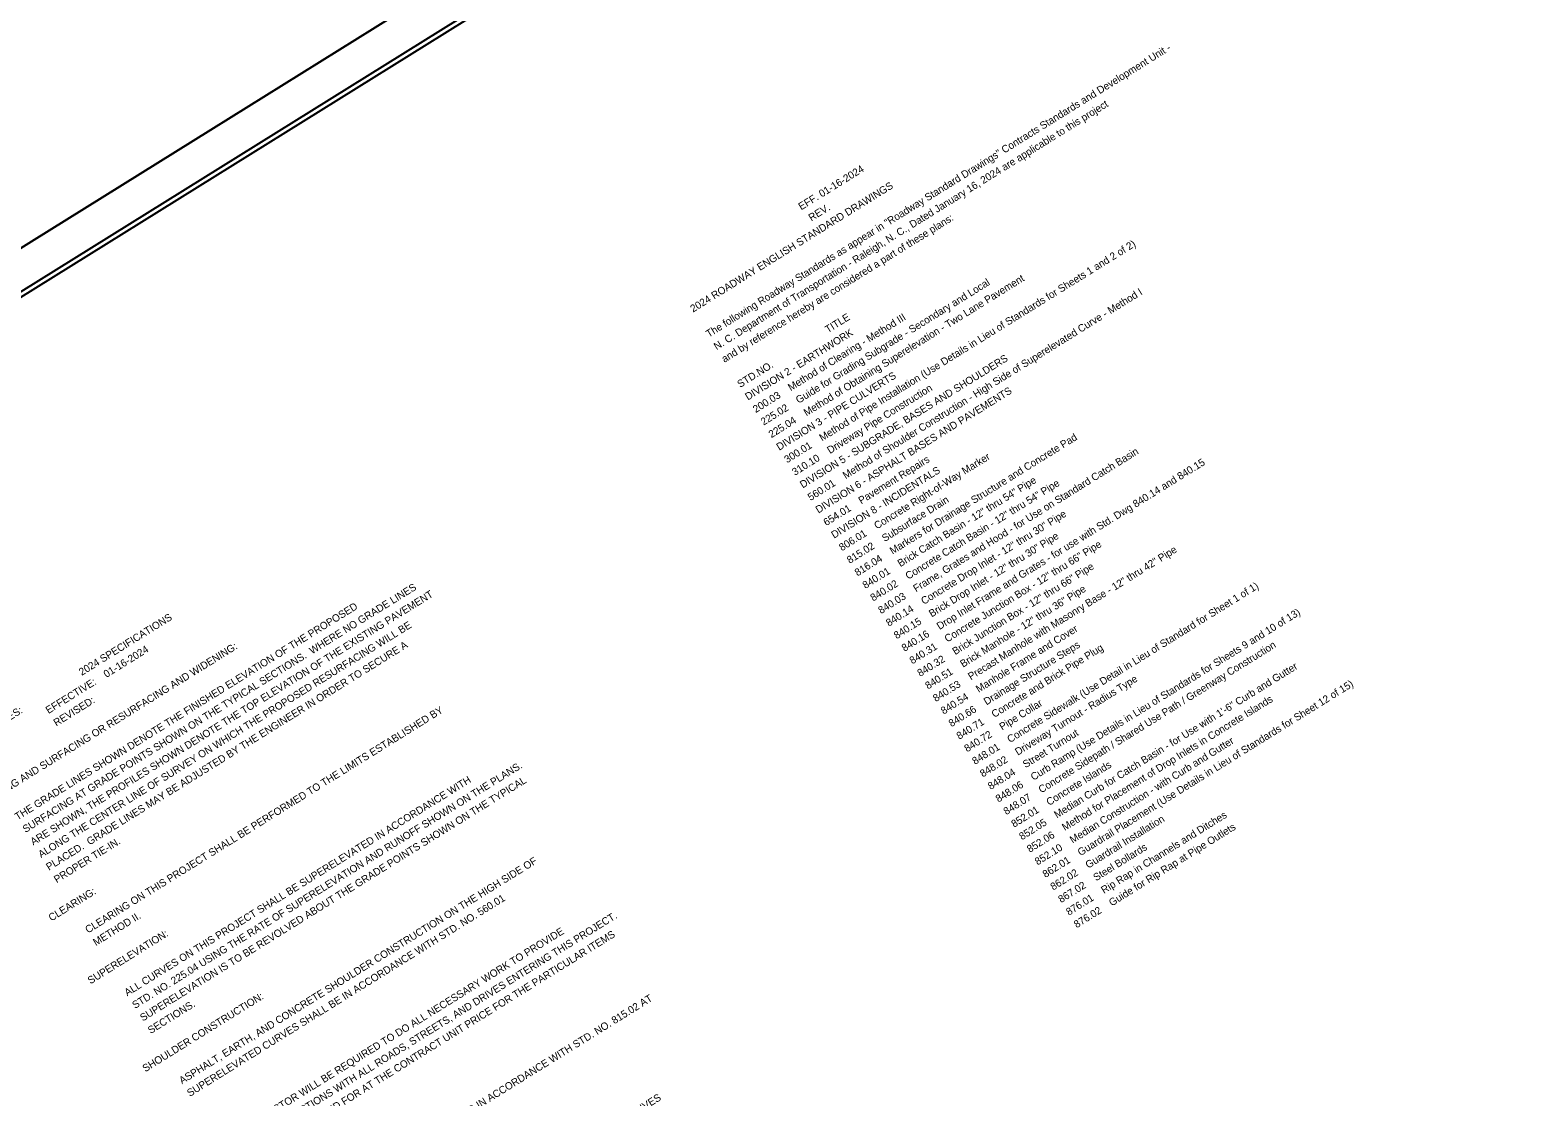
# Model space of a CAD drawing. Extents: x 2047559 to 2049567, y 759970 to 761789.
# Drawn here: x 2048269 to 2049084, y 760880 to 761456 of the extents above; entities that cross this region are included whole.
import ezdxf

# ---------------------------------------------------------------- set-up
doc = ezdxf.new("R2010")
doc.units = 0
for name, color, linetype in [('Sheet Cutting Line CELL', 7, 'Continuous'), ('Sheet Data Text CELL', 7, 'Continuous'), ('Sheet Plan CELL', 7, 'Continuous'), ('Sheet Plot Border Inside CELL', 7, 'Continuous'), ('Sheet Plot Border Outside CELL', 7, 'Continuous')]:
    doc.layers.add(name, color=color, linetype=linetype)

msp = doc.modelspace()

# ---------------------------------------------------------------- linework, layer by layer
at = {"layer": 'Sheet Cutting Line CELL'}
msp.add_line((2048987.97, 761789.33), (2047559, 760899.25), dxfattribs=at)
at = {"layer": 'Sheet Plan CELL'}
msp.add_lwpolyline([(2048985.43, 761761.24), (2047712.23, 760968.18), (2048267.37, 760076.94), (2049540.57, 760870)], close=True, dxfattribs=at)
at = {"layer": 'Sheet Plot Border Inside CELL'}
msp.add_lwpolyline([(2048138.4, 759993.66), (2049552.51, 760874.48), (2048994.72, 761769.97), (2047580.61, 760889.15)], close=True, dxfattribs=at)
at = {"layer": 'Sheet Plot Border Outside CELL'}
msp.add_lwpolyline([(2048137.94, 759969.81), (2049566.9, 760859.89), (2048987.97, 761789.33), (2047559, 760899.25)], close=True, dxfattribs=at)

# ---------------------------------------------------------------- texts
at = {"layer": 'Sheet Data Text CELL'}
for s, height, p in [('The following Roadway Standards as appear in "Roadway Standard Drawings" Contracts Standards and Development Unit -', 3.99997, (2048635.63, 761289.8)), ('N. C. Department of Transportation - Raleigh, N. C., Dated January 16, 2024 are applicable to this project', 3.99997, (2048639.86, 761283.01)), ('                                                     EFF. 01-16-2024', 4, (2048618.71, 761316.96)), ('2024 ROADWAY ENGLISH STANDARD DRAWINGS', 4, (2048627.17, 761303.38)), ('                                                      REV. ', 4, (2048622.94, 761310.17)), ('and by reference hereby are considered a part of these plans:', 4, (2048644.09, 761276.22)), ('300.01    Method of Pipe Installation (Use Details in Lieu of Standards for Sheets 1 and 2 of 2)', 4, (2048677.93, 761221.9)), ('225.02    Guide for Grading Subgrade - Secondary and Local', 4, (2048665.24, 761242.27)), ('225.04    Method of Obtaining Superelevation - Two Lane Pavement', 4, (2048669.47, 761235.48)), ('560.01    Method of Shoulder Construction - High Side of Superelevated Curve - Method I', 4, (2048690.62, 761201.53)), ('STD.NO.                       TITLE', 4, (2048652.55, 761262.64)), ('200.03    Method of Clearing - Method III', 4, (2048661.01, 761249.06)), ('DIVISION 2 - EARTHWORK', 4, (2048656.78, 761255.85)), ('DIVISION 5 - SUBGRADE, BASES AND SHOULDERS', 4, (2048686.39, 761208.32)), ('DIVISION 3 - PIPE CULVERTS', 4, (2048673.7, 761228.69)), ('310.10    Driveway Pipe Construction', 4, (2048682.16, 761215.11)), ('DIVISION 6 - ASPHALT BASES AND PAVEMENTS', 4, (2048694.85, 761194.74)), ('816.04    Markers for Drainage Structure and Concrete Pad', 4, (2048715.99, 761160.79)), ('654.01    Pavement Repairs', 4, (2048699.08, 761187.95)), ('806.01    Concrete Right-of-Way Marker', 4, (2048707.53, 761174.37)), ('840.03    Frame, Grates and Hood - for Use on Standard Catch Basin', 4, (2048728.68, 761140.41)), ('840.16    Drop Inlet Frame and Grates - for use with Std. Dwg 840.14 and 840.15', 4, (2048741.37, 761120.04)), ('DIVISION 8 - INCIDENTALS', 4, (2048703.31, 761181.16)), ('840.01    Brick Catch Basin - 12" thru 54" Pipe', 4, (2048720.22, 761153.99)), ('840.02    Concrete Catch Basin - 12" thru 54" Pipe', 4, (2048724.45, 761147.2)), ('815.02    Subsurface Drain', 4, (2048711.76, 761167.58)), ('840.14    Concrete Drop Inlet - 12" thru 30" Pipe', 4, (2048732.91, 761133.62)), ('840.15    Brick Drop Inlet - 12" thru 30" Pipe', 4, (2048737.14, 761126.83)), ('840.31    Concrete Junction Box - 12" thru 66" Pipe', 4, (2048745.6, 761113.25)), ('840.53    Precast Manhole with Masonry Base - 12" thru 42" Pipe', 4, (2048758.29, 761092.88)), ('840.32    Brick Junction Box - 12" thru 66" Pipe', 4, (2048749.83, 761106.46)), ('         SURFACING AT GRADE POINTS SHOWN ON THE TYPICAL SECTIONS.  WHERE NO GRADE LINES ', 4, (2048255.07, 761015.06)), ('         ARE SHOWN, THE PROFILES SHOWN DENOTE THE TOP ELEVATION OF THE EXISTING PAVEMENT ', 4, (2048259.3, 761008.27)), ('840.51    Brick Manhole - 12" thru 36" Pipe', 4, (2048754.06, 761099.67)), ('848.01    Concrete Sidewalk (Use Detail in Lieu of Standard for Sheet 1 of 1)', 4, (2048779.44, 761058.93)), ('         THE GRADE LINES SHOWN DENOTE THE FINISHED ELEVATION OF THE PROPOSED ', 4, (2048250.84, 761021.85)), ('848.06    Curb Ramp (Use Details in Lieu of Standards for Sheets 9 and 10 of 13)', 4, (2048792.13, 761038.56)), ('GENERAL NOTES:                         2024 SPECIFICATIONS', 4, (2048225.46, 761062.59)), ('         ALONG THE CENTER LINE OF SURVEY ON WHICH THE PROPOSED RESURFACING WILL BE ', 4, (2048263.53, 761001.48)), ('840.54    Manhole Frame and Cover', 4, (2048762.52, 761086.09)), ('         PLACED.  GRADE LINES MAY BE ADJUSTED BY THE ENGINEER IN ORDER TO SECURE A ', 4, (2048267.76, 760994.69)), ('GRADING AND SURFACING OR RESURFACING AND WIDENING:  ', 4, (2048242.38, 761035.43)), ('                                       EFFECTIVE:    01-16-2024', 4, (2048229.69, 761055.8)), ('840.66    Drainage Structure Steps', 4, (2048766.75, 761079.3)), ('840.71    Concrete and Brick Pipe Plug', 4, (2048770.98, 761072.51)), ('848.07    Concrete Sidepath / Shared Use Path / Greenway Construction', 4, (2048796.36, 761031.77)), ('852.05    Median Curb for Catch Basin - for Use with 1\'-6" Curb and Gutter', 4, (2048804.82, 761018.19)), ('848.02    Driveway Turnout - Radius Type', 4, (2048783.67, 761052.14)), ('862.01    Guardrail Placement (Use Details in Lieu of Standards for Sheet 12 of 15)', 4, (2048817.51, 760997.82)), ('                                       REVISED:      ', 4, (2048233.92, 761049.01)), ('840.72    Pipe Collar', 4, (2048775.21, 761065.72)), ('852.06    Method for Placement of Drop Inlets in Concrete Islands', 4, (2048809.05, 761011.4)), ('         CLEARING ON THIS PROJECT SHALL BE PERFORMED TO THE LIMITS ESTABLISHED BY ', 4, (2048288.91, 760960.74)), ('848.04    Street Turnout', 4, (2048787.9, 761045.35)), ('852.10    Median Construction - with Curb and Gutter', 4, (2048813.28, 761004.61)), ('852.01    Concrete Islands', 4, (2048800.59, 761024.98)), ('         ALL CURVES ON THIS PROJECT SHALL BE SUPERELEVATED IN ACCORDANCE WITH', 4, (2048310.06, 760926.78)), ('         STD. NO. 225.04 USING THE RATE OF SUPERELEVATION AND RUNOFF SHOWN ON THE PLANS.', 4, (2048314.29, 760919.99)), ('         SUPERELEVATION IS TO BE REVOLVED ABOUT THE GRADE POINTS SHOWN ON THE TYPICAL ', 4, (2048318.52, 760913.2)), ('862.02    Guardrail Installation', 4, (2048821.73, 760991.02)), ('876.01    Rip Rap in Channels and Ditches', 4, (2048830.19, 760977.44)), ('876.02    Guide for Rip Rap at Pipe Outlets', 4, (2048834.42, 760970.65)), ('         PROPER TIE-IN.  ', 4, (2048271.99, 760987.9)), ('867.02    Steel Bollards', 4, (2048825.96, 760984.23)), ('         ASPHALT, EARTH, AND CONCRETE SHOULDER CONSTRUCTION ON THE HIGH SIDE OF', 4, (2048339.66, 760879.25)), ('CLEARING:  ', 4, (2048280.45, 760974.32)), ('         SUPERELEVATED CURVES SHALL BE IN ACCORDANCE WITH STD. NO. 560.01', 4, (2048343.89, 760872.46)), ('         METHOD II.', 4, (2048293.14, 760953.95)), ('         SUITABLE CONNECTIONS WITH ALL ROADS, STREETS, AND DRIVES ENTERING THIS PROJECT.  ', 4, (2048365.04, 760838.51)), ('         THE CONTRACTOR WILL BE REQUIRED TO DO ALL NECESSARY WORK TO PROVIDE ', 4, (2048360.81, 760845.3)), ('SUPERELEVATION:  ', 4, (2048301.6, 760940.36)), ('         THIS WORK WILL BE PAID FOR AT THE CONTRACT UNIT PRICE FOR THE PARTICULAR ITEMS ', 4, (2048369.27, 760831.72)), ('SHOULDER CONSTRUCTION:  ', 4, (2048331.2, 760892.83)), ('         SECTIONS.  ', 4, (2048322.74, 760906.41)), ('         SUBSURFACE DRAINS SHALL BE CONSTRUCTED IN ACCORDANCE WITH STD. NO. 815.02 AT ', 4, (2048390.42, 760797.77)), ('         USING 3 FOOT RADII OR RADII AS SHOWN ON THE PLANS.  LOCATIONS OF DRIVES', 4, (2048415.8, 760757.02))]:
    msp.add_text(s, height=height, rotation=31.91803, dxfattribs=at).set_placement(p)

doc.saveas('drawing.dxf')
